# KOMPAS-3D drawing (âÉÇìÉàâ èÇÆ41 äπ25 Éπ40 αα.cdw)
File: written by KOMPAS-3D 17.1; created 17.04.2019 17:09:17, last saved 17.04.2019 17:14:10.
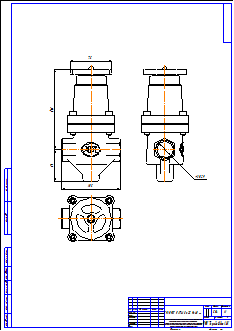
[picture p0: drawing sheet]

Sheet 1: A2, portrait

Title block, sheet 1: name: ГРАНРЕГ КАТ41 Ду25 Ру40 рр; material: Внимание! Данный продукт является объектом авторского права ООО «Торговый Дом АДЛ». / Запрещается изменение, копирование, распространение / (в том числе путем копирования на другие сайты и ресурсы в Интернете) / или любое иное использование информации и объектов без предварительного / согласия правообладателя (ООО «Торговый Дом АДЛ»).; mass: 5,04; sheets: 1; organisation: ООО "Торговый дом АДЛ"; sheet format: A2; stored path: \\adlc.lan\data\АДЛ_ПКД\3D-модели\ADL production\Клапаны КАТ ГРАНРЕГ\КАТ41\KOMPAS 2D\ГРАНРЕГ КАТ41 Ду25 Ру40 рр.cdw

Views: Спереди 1, Проекционный вид 2, Проекционный вид 3
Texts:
  user
Dimensions and other numbers on the sheet: 75; 105; 57; 145; 30,29; 1:1; 1; 5,04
